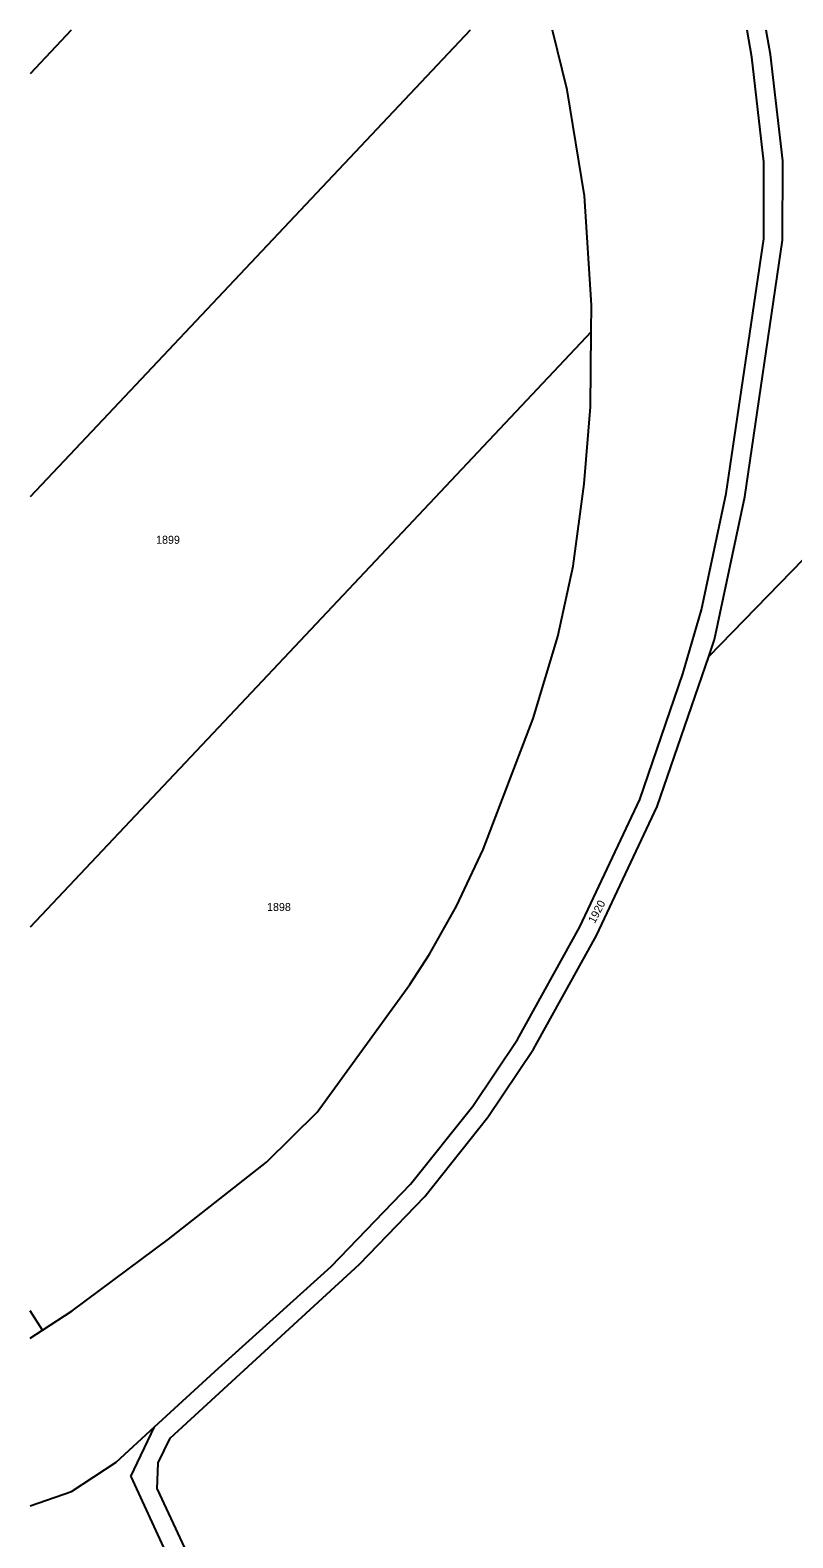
# Model space of a CAD drawing. Extents: x -801853 to -800578, y -1017479 to -1016338.
# Drawn here: x -801848 to -801685.9, y -1016658 to -1016337.6 of the extents above; entities that cross this region are included whole.
import ezdxf

# ---------------------------------------------------------------- set-up
doc = ezdxf.new("R2010")
doc.units = 0
doc.layers.add('KN_HRANICE', color=7, linetype='Continuous')
doc.layers.add('KN_PARCELY', color=7, linetype='Continuous')

msp = doc.modelspace()

# ---------------------------------------------------------------- linework, layer by layer
at = {"layer": 'KN_HRANICE'}
for p, q in [((-801839.3, -1016337.63), (-801848.02, -1016346.88)), ((-801754.51, -1016337.63), (-801838.44, -1016426.64)), ((-801733.9, -1016350.31), (-801736.99, -1016337.63)), ((-801694.66, -1016343.35), (-801695.67, -1016337.63)), ((-801690.7, -1016342.78), (-801691.61, -1016337.63)), ((-801692.09, -1016365.61), (-801694.66, -1016343.35)), ((-801688.09, -1016365.37), (-801690.7, -1016342.78)), ((-801730.24, -1016372.86), (-801733.9, -1016350.31)), ((-801692.1, -1016381.98), (-801692.09, -1016365.61)), ((-801688.1, -1016382.28), (-801688.09, -1016365.37)), ((-801728.75, -1016396.07), (-801730.24, -1016372.86)), ((-801700.09, -1016436.1), (-801692.1, -1016381.98)), ((-801696.15, -1016436.79), (-801688.1, -1016382.28)), ((-801703.82, -1016470.7), (-801619.17, -1016383.72)), ((-801728.8, -1016401.76), (-801728.75, -1016396.07)), ((-801728.8, -1016401.76), (-801803.31, -1016480.81)), ((-801728.94, -1016417.64), (-801728.8, -1016401.76)), ((-801730.31, -1016434.02), (-801728.94, -1016417.64)), ((-801838.44, -1016426.64), (-801848.02, -1016436.79)), ((-801732.61, -1016451.53), (-801730.31, -1016434.02)), ((-801705.33, -1016460.78), (-801700.09, -1016436.1)), ((-801702.59, -1016467.12), (-801696.15, -1016436.79)), ((-801735.86, -1016466.43), (-801732.61, -1016451.53)), ((-801709.31, -1016474.4), (-801705.33, -1016460.78)), ((-801741.15, -1016483.87), (-801735.86, -1016466.43)), ((-801703.82, -1016470.7), (-801702.59, -1016467.12)), ((-801714.74, -1016502.58), (-801703.82, -1016470.7)), ((-801718.45, -1016501.08), (-801709.31, -1016474.4)), ((-801803.31, -1016480.81), (-801848.02, -1016528.24)), ((-801751.76, -1016511.75), (-801741.15, -1016483.87)), ((-801731.22, -1016528.13), (-801718.45, -1016501.08)), ((-801727.66, -1016529.96), (-801714.74, -1016502.58)), ((-801757.41, -1016523.78), (-801751.76, -1016511.75)), ((-801763.15, -1016533.96), (-801757.41, -1016523.78)), ((-801744.48, -1016552.1), (-801731.22, -1016528.13)), ((-801741.05, -1016554.17), (-801727.66, -1016529.96)), ((-801767.33, -1016540.43), (-801763.15, -1016533.96)), ((-801787.01, -1016567.5), (-801767.33, -1016540.43)), ((-801753.96, -1016566.26), (-801744.48, -1016552.1)), ((-801750.73, -1016568.62), (-801741.05, -1016554.17)), ((-801797.78, -1016578.18), (-801787.01, -1016567.5)), ((-801767.17, -1016582.79), (-801753.96, -1016566.26)), ((-801764.17, -1016585.44), (-801750.73, -1016568.62)), ((-801818.58, -1016594.49), (-801797.78, -1016578.18)), ((-801784.07, -1016600.33), (-801767.17, -1016582.79)), ((-801778.04, -1016599.84), (-801764.17, -1016585.44)), ((-801839.08, -1016609.76), (-801818.58, -1016594.49)), ((-801818.29, -1016636.8), (-801778.04, -1016599.84)), ((-801807.99, -1016621.91), (-801784.07, -1016600.33)), ((-801845.36, -1016613.85), (-801848.02, -1016609.76)), ((-801845.36, -1016613.85), (-801839.08, -1016609.76)), ((-801848.02, -1016615.57), (-801845.36, -1016613.85)), ((-801821.56, -1016634.38), (-801807.99, -1016621.91)), ((-801829.76, -1016641.92), (-801821.56, -1016634.38)), ((-801826.65, -1016644.95), (-801821.56, -1016634.38)), ((-801820.81, -1016642.04), (-801818.29, -1016636.8)), ((-801839.2, -1016648.11), (-801829.76, -1016641.92)), ((-801821.01, -1016647.6), (-801820.81, -1016642.04)), ((-801826.65, -1016644.95), (-801807.71, -1016685.75)), ((-801848.02, -1016651.14), (-801839.2, -1016648.11)), ((-801821.01, -1016647.6), (-801803.99, -1016684.26))]:
    msp.add_line(p, q, dxfattribs=at)

# ---------------------------------------------------------------- texts
at = {"layer": 'KN_PARCELY'}
for s, p in [('1899', (-801821.25, -1016446.76)), ('1898', (-801797.67, -1016524.78))]:
    msp.add_text(s, height=1.7, dxfattribs=at).set_placement(p)
msp.add_text('1920', height=1.7, rotation=62.739, dxfattribs=at).set_placement((-801728.01, -1016527.55))

doc.saveas('drawing.dxf')
